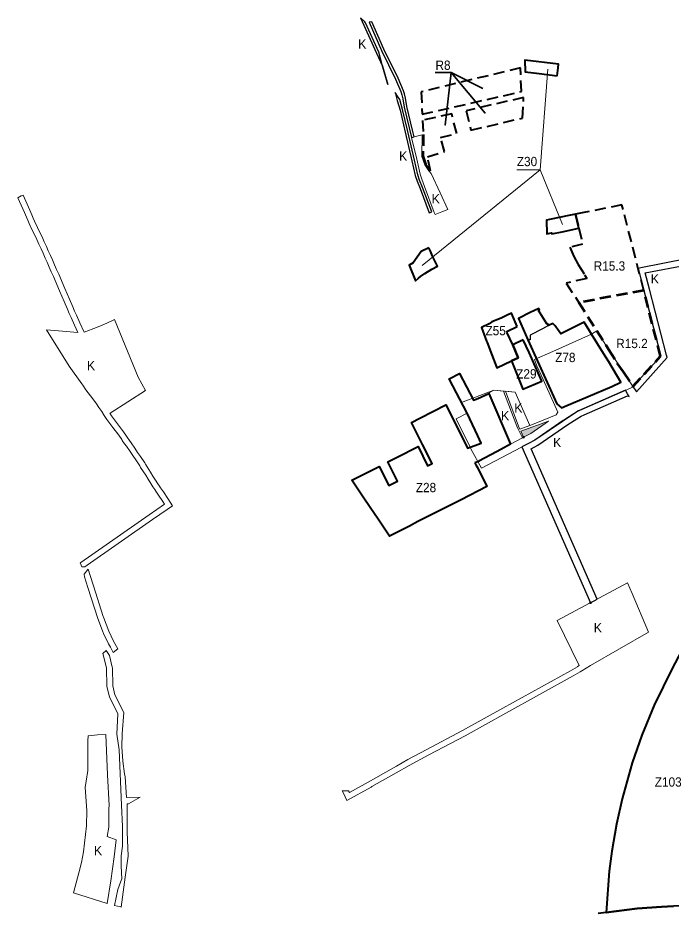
# Model space of a CAD drawing. Extents: x -650276 to -642489, y -1074311 to -1066658.
# Drawn here: x -649558 to -647871, y -1068970 to -1066658 of the extents above; entities that cross this region are included whole.
import ezdxf

# ---------------------------------------------------------------- set-up
doc = ezdxf.new("R2010")
doc.units = 0
doc.header["$LTSCALE"] = 9.6
doc.header["$PDMODE"] = 32
doc.header["$PDSIZE"] = 4.8
doc.linetypes.add('MEDIUM_DASHED', pattern=[4.5, 3, -1.5])
for name, color, linetype, lineweight in [('42', 7, 'Continuous', 25), ('44', 7, 'Continuous', 40), ('45', 7, 'Continuous', 40), ('46', 7, 'Continuous', 13), ('47', 7, 'Continuous', 13), ('48', 7, 'Continuous', 13), ('61', 7, 'MEDIUM_DASHED', 40), ('62', 7, 'Continuous', 35), ('63', 7, 'Continuous', 13)]:
    doc.layers.add(name, color=color, linetype=linetype, lineweight=lineweight)

msp = doc.modelspace()

# ---------------------------------------------------------------- hatches: boundary and pattern name
at = {"layer": '47'}
msp.add_hatch(color=256, dxfattribs=at).paths.add_polyline_path([(-648258.96, -1067725.37), (-648251.711, -1067741.124), (-648233.264, -1067731.288), (-648187.139, -1067699.179)])

# ---------------------------------------------------------------- linework, layer by layer
at = {"layer": '42'}
msp.add_lwpolyline([(-648153.98, -1067665.43), (-648149.933, -1067663.646), (-648146.21, -1067661.3), (-648023.96, -1067610.13), (-648000.63, -1067599.14), (-648031.77, -1067546.6), (-648045.04, -1067525.15), (-648076.32, -1067474.6), (-648081.31, -1067466.54), (-648095.28, -1067444.06), (-648133.56, -1067463.2), (-648150.46, -1067471.66), (-648155.85, -1067474.35), (-648164.24, -1067462.15), (-648166.97, -1067458.18), (-648170.38, -1067453.23), (-648175.94, -1067446.89), (-648187.44, -1067452.8), (-648203.39, -1067460.99), (-648234.68, -1067477.06), (-648234.87, -1067489.9), (-648240.51, -1067489.9), (-648166.173, -1067654.853)], close=True, dxfattribs=at)
at = {"layer": '44'}
for points in [[(-647801.168, -1068218.237), (-647843.6, -1068292.629), (-647868.214, -1068337.803), (-647914.339, -1068432.512), (-647946.187, -1068510.254), (-647971.074, -1068581.98), (-647997.27, -1068674.747), (-648011.775, -1068739.718), (-648023.914, -1068809.332), (-648030.73, -1068861.213), (-648038.596, -1068968.281), (-647958.168, -1068957.73)], [(-647749.978, -1068953.416), (-647850.043, -1068951.099), (-647864.531, -1068951.823), (-647895.901, -1068953.392), (-647958.168, -1068957.73), (-648038.596, -1068968.281), (-648038.596, -1068968.281), (-648038.746, -1068968.301), (-648058.764, -1068970.927)], [(-647958.168, -1068957.73), (-647895.901, -1068953.392), (-647864.531, -1068951.823)]]:
    msp.add_lwpolyline(points, dxfattribs=at)
at = {"layer": '45'}
for points in [[(-648165.33, -1066807.74), (-648162.8, -1066786.8), (-648161.58, -1066777.41), (-648248.77, -1066767.43), (-648247.78, -1066797.53), (-648211.58, -1066802.18)], [(-648165.33, -1066807.74), (-648162.8, -1066786.8), (-648161.58, -1066777.41), (-648248.77, -1066767.43), (-648247.78, -1066797.53), (-648211.58, -1066802.18)], [(-648185.185, -1067178.687), (-648193.02, -1067180.66), (-648191.44, -1067215.62), (-648179.42, -1067213.37), (-648179, -1067215.71), (-648152.5, -1067210.23), (-648109.1, -1067201.21), (-648117.51, -1067165.42), (-648131.01, -1067167.84)], [(-648185.185, -1067178.687), (-648193.02, -1067180.66), (-648191.44, -1067215.62), (-648179.42, -1067213.37), (-648179, -1067215.71), (-648152.5, -1067210.23), (-648109.1, -1067201.21), (-648117.51, -1067165.42), (-648131.01, -1067167.84)], [(-648496.55, -1067251.53), (-648516.47, -1067261.54), (-648536.84, -1067290.29), (-648547.17, -1067296.68), (-648531.51, -1067337.57), (-648523.55, -1067330.33), (-648518.55, -1067326.3), (-648507.25, -1067318.35), (-648488.66, -1067307.11), (-648474.69, -1067299.66), (-648486.79, -1067273.26), (-648492.62, -1067260.53)], [(-648496.55, -1067251.53), (-648516.47, -1067261.54), (-648536.84, -1067290.29), (-648547.17, -1067296.68), (-648531.51, -1067337.57), (-648523.55, -1067330.33), (-648518.55, -1067326.3), (-648507.25, -1067318.35), (-648488.66, -1067307.11), (-648474.69, -1067299.66), (-648486.79, -1067273.26), (-648492.62, -1067260.53)], [(-648153.98, -1067665.43), (-648149.933, -1067663.646), (-648146.21, -1067661.3), (-648023.96, -1067610.13), (-648000.63, -1067599.14), (-648031.77, -1067546.6), (-648045.04, -1067525.15), (-648076.32, -1067474.6), (-648081.31, -1067466.54), (-648095.28, -1067444.06), (-648133.56, -1067463.2), (-648150.46, -1067471.66), (-648155.85, -1067474.35), (-648164.24, -1067462.15), (-648166.97, -1067458.18), (-648170.38, -1067453.23), (-648175.94, -1067446.89), (-648187.44, -1067452.8), (-648190.23, -1067447.83), (-648191.46, -1067448.59), (-648213.34, -1067413.46), (-648210.48, -1067411.68), (-648212.32, -1067408.39), (-648234.808, -1067419.29), (-648265.197, -1067434.03), (-648240.51, -1067489.9), (-648166.173, -1067654.853)], [(-648153.98, -1067665.43), (-648149.933, -1067663.646), (-648146.21, -1067661.3), (-648023.96, -1067610.13), (-648000.63, -1067599.14), (-648031.77, -1067546.6), (-648045.04, -1067525.15), (-648076.32, -1067474.6), (-648081.31, -1067466.54), (-648095.28, -1067444.06), (-648133.56, -1067463.2), (-648150.46, -1067471.66), (-648155.85, -1067474.35), (-648164.24, -1067462.15), (-648166.97, -1067458.18), (-648170.38, -1067453.23), (-648175.94, -1067446.89), (-648187.44, -1067452.8), (-648190.23, -1067447.83), (-648191.46, -1067448.59), (-648213.34, -1067413.46), (-648210.48, -1067411.68), (-648212.32, -1067408.39), (-648234.808, -1067419.29), (-648265.197, -1067434.03), (-648240.51, -1067489.9), (-648166.173, -1067654.853)], [(-648253.1, -1067489.23), (-648279.86, -1067502.11), (-648265.757, -1067535.555), (-648282.863, -1067543.596), (-648254.04, -1067616.96), (-648204.88, -1067596.54), (-648237.81, -1067522.42)]]:
    msp.add_lwpolyline(points, close=True, dxfattribs=at)
for points in [[(-648268.67, -1067455.43), (-648283.21, -1067420.88), (-648295.66, -1067426.76), (-648309.57, -1067433.34), (-648333.48, -1067443.28), (-648341.15, -1067448.14)], [(-648341.15, -1067448.14), (-648361, -1067457.36), (-648347.51, -1067492.87)], [(-648279.86, -1067502.11), (-648294.04, -1067471.35), (-648295.409, -1067468.129), (-648268.67, -1067455.43)], [(-648347.51, -1067492.87), (-648346.27, -1067496.14), (-648334.09, -1067528.2), (-648321.36, -1067561.69), (-648282.863, -1067543.596)], [(-648282.863, -1067543.596), (-648265.757, -1067535.555), (-648279.86, -1067502.11)], [(-648433.183, -1067696.369), (-648396.605, -1067769.277), (-648387.04, -1067765.67), (-648361.08, -1067755.88), (-648369.832, -1067737.624), (-648397.98, -1067678.79), (-648443.83, -1067589.92), (-648417.12, -1067576.17), (-648381.535, -1067645.274), (-648369.949, -1067640.851), (-648342.023, -1067628.096), (-648285.254, -1067759.008), (-648310.511, -1067772.476), (-648321.623, -1067778.399), (-648367.811, -1067802.994), (-648370.113, -1067804.22), (-648377.422, -1067807.337)], [(-648377.422, -1067807.337), (-648374.84, -1067812.43), (-648371.27, -1067819.47), (-648346.57, -1067868.56), (-648413.41, -1067902.53), (-648524.72, -1067958.93), (-648546.76, -1067970.44), (-648597.93, -1067996.72), (-648629.22, -1067950.214), (-648635.249, -1067941.252), (-648664.41, -1067897.91), (-648695.27, -1067852.04), (-648668.085, -1067838.186), (-648624.76, -1067816.11), (-648600.14, -1067865.29), (-648577.78, -1067854.07), (-648602.3, -1067804.83), (-648580.14, -1067793.61), (-648524.44, -1067765.11), (-648499.7, -1067814.37), (-648488.49, -1067808.76), (-648513.23, -1067759.38), (-648516.73, -1067752.57), (-648541.86, -1067702.86), (-648519.63, -1067691.58), (-648452.72, -1067657.62), (-648433.183, -1067696.369)]]:
    msp.add_lwpolyline(points, dxfattribs=at)
at = {"layer": '46'}
msp.add_lwpolyline([(-648269.459, -1067050.713), (-648208.812, -1067050.713), (-648188.893, -1066790.602), (-648208.812, -1067050.713), (-648151.62, -1067191.569), (-648208.812, -1067050.713), (-648513.485, -1067297.251)], dxfattribs=at)
msp.add_lwpolyline([(-648269.459, -1067050.713), (-648208.812, -1067050.713), (-648188.893, -1066790.602), (-648208.812, -1067050.713), (-648151.62, -1067191.569), (-648208.812, -1067050.713), (-648513.485, -1067297.251)], dxfattribs=at)
at = {"layer": '47'}
msp.add_line((-648108.158, -1068330.583), (-648112.198, -1068333.037), dxfattribs=at)
at = {"layer": '47', "lineweight": 25}
for points in [[(-648602.97, -1066830.11), (-648616.86, -1066779.79), (-648625.44, -1066746.45), (-648659.95, -1066670.89), (-648662.46, -1066668.53), (-648673.407, -1066658.275), (-648631.791, -1066749.394)], [(-648534.701, -1066965.077), (-648538.812, -1066947.891), (-648553.323, -1066887.238), (-648556.637, -1066865.397), (-648559.94, -1066854.66), (-648562.542, -1066846.219), (-648576.145, -1066813.802), (-648612.763, -1066739.165), (-648643.925, -1066668.483), (-648651.042, -1066669.551), (-648651.1, -1066669.56)], [(-648651.1, -1066669.56), (-648619.11, -1066742.12), (-648582.52, -1066816.7)], [(-648631.791, -1066749.394), (-648616.104, -1066782.727), (-648602.97, -1066830.11)], [(-648582.52, -1066816.7), (-648569.13, -1066848.61), (-648566.63, -1066856.72), (-648563.48, -1066866.96), (-648560.2, -1066888.58), (-648541.521, -1066966.657), (-648534.701, -1066965.077)], [(-648571.96, -1066869.37), (-648577.99, -1066860.17), (-648583.94, -1066851.11)], [(-648583.94, -1066851.11), (-648578.702, -1066871.259), (-648571.167, -1066896.326), (-648557.816, -1066953.444)], [(-648489.1, -1067158.84), (-648512.95, -1067095.97), (-648520.4, -1067077.42), (-648524.93, -1067063.35), (-648533.66, -1067026), (-648551, -1066951.85), (-648564.4, -1066894.52), (-648571.96, -1066869.37)], [(-648557.816, -1066953.444), (-648540.476, -1067027.594), (-648531.681, -1067065.222)], [(-648531.681, -1067065.222), (-648526.988, -1067079.8), (-648519.471, -1067098.516), (-648495.644, -1067161.326), (-648489.1, -1067158.84)], [(-647882.66, -1067529.231), (-647926.759, -1067358.379), (-647937.355, -1067316.774), (-647828.376, -1067295.406), (-647828.104, -1067295.352), (-647831.28, -1067280.69), (-647948.488, -1067303.671)], [(-647948.488, -1067303.671), (-647955.805, -1067305.106), (-647941.289, -1067362.104)], [(-647941.289, -1067362.104), (-647897.637, -1067531.223), (-647969.29, -1067609.79), (-647959.832, -1067623.65)], [(-647959.832, -1067623.65), (-647881.085, -1067535.333), (-647882.66, -1067529.231)], [(-647978.705, -1067635.817), (-647982.95, -1067628.73), (-647988.334, -1067619.747), (-648046.773, -1067645.314)], [(-648046.773, -1067645.314), (-648110.36, -1067673.133), (-648146.127, -1067695.8), (-648146.146, -1067695.813), (-648149.529, -1067698.132), (-648222.53, -1067748.178)], [(-648095.475, -1067682.994), (-647983.06, -1067633.813), (-647978.705, -1067635.817)], [(-648232.676, -1067770.513), (-648215.115, -1067761.28), (-648137.869, -1067708.325), (-648114.323, -1067693.403), (-648103.298, -1067686.416), (-648095.475, -1067682.994)], [(-648238.748, -1067756.759), (-648256.499, -1067766.091), (-648079.002, -1068168.139)], [(-648222.53, -1067748.178), (-648222.872, -1067748.412), (-648238.748, -1067756.759)], [(-648079.002, -1068168.139), (-648061.329, -1068158.649), (-648232.676, -1067770.513)]]:
    msp.add_lwpolyline(points, dxfattribs=at)
at = {"layer": '47'}
for points in [[(-648490.23, -1067060.06), (-648496.87, -1067053.5), (-648506.78, -1067037.81), (-648514.38, -1067016.2), (-648513.842, -1066960.243), (-648541.52, -1066966.657), (-648528.01, -1067023.13)], [(-648528.01, -1067023.13), (-648518.72, -1067061.99), (-648514.86, -1067074.83), (-648507.88, -1067093.9), (-648483.31, -1067160.63), (-648480.57, -1067166.13)], [(-648480.57, -1067166.13), (-648462.97, -1067159.24), (-648447.66, -1067153.25), (-648467.56, -1067110.02), (-648490.23, -1067060.06)], [(-649545.203, -1067115.647), (-649549.7, -1067118.05), (-649558.469, -1067122.73), (-649541.537, -1067160.722), (-649536.075, -1067172.622), (-649532.831, -1067180.855), (-649529.013, -1067189.389), (-649521.663, -1067206.124), (-649514.869, -1067218.957), (-649509.44, -1067230.141), (-649504.224, -1067242.225), (-649498.572, -1067254.427), (-649493.526, -1067265.611), (-649487.812, -1067278.312), (-649482.963, -1067288.934), (-649477.677, -1067301.655), (-649472.327, -1067313.644), (-649466.703, -1067326.24), (-649451.059, -1067363.074), (-649439.265, -1067390.397), (-649430.531, -1067410.689), (-649425.804, -1067421.21), (-649421.071, -1067431.944), (-649411.913, -1067451.746), (-649403.34, -1067470.579)], [(-649387.17, -1067469.894), (-649398.28, -1067445.49), (-649407.4, -1067425.77), (-649412.1, -1067415.11), (-649416.8, -1067404.65), (-649425.49, -1067384.46), (-649437.27, -1067357.17), (-649452.95, -1067320.25), (-649458.63, -1067307.53), (-649463.9, -1067295.72), (-649469.21, -1067282.94), (-649474.15, -1067272.12), (-649479.85, -1067259.45), (-649484.93, -1067248.19), (-649490.53, -1067236.1), (-649495.8, -1067223.89), (-649501.49, -1067212.17), (-649508.15, -1067199.59), (-649515.3, -1067183.31), (-649519, -1067175.04), (-649522.27, -1067166.74), (-649527.87, -1067154.54), (-649545.203, -1067115.647)], [(-649321.3, -1067679), (-649320.47, -1067678.44), (-649228.52, -1067620.294), (-649247.518, -1067586.255), (-649308.75, -1067437.11), (-649329.068, -1067446.175), (-649355.44, -1067457.94), (-649387.17, -1067469.894)], [(-649403.34, -1067470.579), (-649453.39, -1067466.13), (-649484.28, -1067463.88), (-649425.69, -1067557.7), (-649393.23, -1067603.28), (-649391.04, -1067606.27), (-649382.53, -1067618.33), (-649364.69, -1067641.98), (-649355.46, -1067654.85), (-649349.12, -1067663.84), (-649341.81, -1067674.33), (-649335.26, -1067685.21), (-649333.74, -1067687.4)], [(-649333.74, -1067687.4), (-649328.34, -1067694.79), (-649317.99, -1067708.85), (-649312.91, -1067715.45), (-649298.02, -1067735.58), (-649290.15, -1067746.92), (-649288.63, -1067748.97), (-649282.85, -1067757.79), (-649278.14, -1067764.31), (-649268.46, -1067777.97), (-649261.48, -1067788.47), (-649253.98, -1067799.2), (-649243.37, -1067815.17), (-649241.28, -1067818.7), (-649228.27, -1067839.26), (-649222.11, -1067849.12), (-649215.32, -1067859.99), (-649209.39, -1067869.34), (-649204.87, -1067875.85), (-649202.02, -1067880.07), (-649194.77, -1067890.67), (-649184, -1067906.88), (-649179.96, -1067913.35), (-649219.088, -1067940.964), (-649395.729, -1068064.23), (-649397.466, -1068065.442), (-649394.83, -1068071.05), (-649392.88, -1068075.9), (-649385.41, -1068075.32), (-649379.295, -1068071.053), (-649210.54, -1067953.29), (-649172.99, -1067927.41), (-649159.179, -1067918.309), (-649171.389, -1067898.756), (-649182.332, -1067882.285), (-649189.614, -1067871.638), (-649192.493, -1067867.375), (-649196.89, -1067861.042), (-649202.625, -1067852), (-649209.388, -1067841.173), (-649215.571, -1067831.276), (-649228.486, -1067810.867), (-649230.661, -1067807.193), (-649241.584, -1067790.752), (-649249.085, -1067780.02), (-649256.092, -1067769.48), (-649265.941, -1067755.582), (-649270.491, -1067749.283), (-649276.322, -1067740.385), (-649277.961, -1067738.175), (-649285.826, -1067726.842), (-649300.936, -1067706.414), (-649306.005, -1067699.828), (-649316.244, -1067685.919), (-649321.3, -1067679)], [(-649376.467, -1068081.552), (-649377.77, -1068082.44), (-649387.46, -1068094.51), (-649386.74, -1068101.31), (-649377.81, -1068129), (-649352.11, -1068208.65)], [(-649352.11, -1068208.65), (-649339.94, -1068241.13), (-649337.52, -1068247.59), (-649324.66, -1068274.3), (-649319.551, -1068283.382), (-649312.087, -1068296.653), (-649300.305, -1068287.002), (-649311.352, -1068267.362), (-649323.711, -1068241.693), (-649337.178, -1068205.751), (-649337.942, -1068203.713), (-649363.534, -1068124.395), (-649371.987, -1068098.185), (-649376.467, -1068081.552)], [(-648101.42, -1068344.28), (-648079.33, -1068330.03), (-647929.45, -1068244.16), (-647971.35, -1068144.48), (-647982.969, -1068116.575), (-648165.28, -1068214.465), (-648108.158, -1068330.583)], [(-649330.038, -1068291.976), (-649339.046, -1068299.359), (-649329.644, -1068336.779), (-649328.386, -1068384.468), (-649321.727, -1068411.472), (-649299.894, -1068454.728), (-649302.681, -1068507.363)], [(-649289.24, -1068506.8), (-649284.59, -1068451.76), (-649307.57, -1068406.23), (-649313.42, -1068382.51), (-649314.27, -1068336.41), (-649314.693, -1068334.727), (-649322.18, -1068304.93), (-649330.038, -1068291.976)], [(-648112.198, -1068333.037), (-648112.92, -1068333.424), (-648131.034, -1068344.388), (-648305.242, -1068440.3), (-648410.111, -1068498.408), (-648503.768, -1068547.914), (-648551.041, -1068573.16)], [(-648547.25, -1068588.14), (-648496.73, -1068561.16), (-648402.97, -1068511.6), (-648297.99, -1068453.43), (-648123.53, -1068357.38), (-648105.49, -1068346.46), (-648101.42, -1068344.28)], [(-649327.679, -1068945.222), (-649318.13, -1068886.42), (-649314.07, -1068855.33), (-649310.01, -1068824.2), (-649304.66, -1068780.33), (-649327.8, -1068771.82), (-649323.68, -1068748.06), (-649323.1, -1068699.28), (-649323.02, -1068692.1), (-649326.53, -1068612.89), (-649331.151, -1068508.557), (-649353.17, -1068509.48), (-649376.77, -1068511.96), (-649377.52, -1068525.1), (-649377.56, -1068564.89), (-649378.08, -1068601.24), (-649382.46, -1068629.34), (-649384.31, -1068644.92), (-649379.97, -1068704.98), (-649381.06, -1068744.69), (-649383.78, -1068766.6)], [(-649302.681, -1068507.363), (-649296.55, -1068548.09), (-649290.93, -1068690.93), (-649287.98, -1068745.74), (-649288.19, -1068786.39), (-649288.24, -1068796.6), (-649291.64, -1068821.88), (-649291.87, -1068848.02), (-649290.28, -1068880.82), (-649293.33, -1068889.65), (-649299.91, -1068908.66), (-649308.65, -1068950), (-649293.04, -1068953.81), (-649291.32, -1068954.23), (-649281.01, -1068876.69), (-649273.66, -1068822.58), (-649275.96, -1068759.73), (-649276.43, -1068688.29), (-649276.474, -1068687.673), (-649272.755, -1068687.618)], [(-649277.655, -1068670.983), (-649281.4, -1068618.05), (-649282.97, -1068610.04), (-649287.71, -1068577.14), (-649289.74, -1068540.2), (-649289.24, -1068506.8)], [(-648551.041, -1068573.16), (-648580.062, -1068590.087), (-648588.022, -1068594.571), (-648653.034, -1068631.191), (-648701.568, -1068658.36), (-648703.816, -1068653.711), (-648720.238, -1068654.205)], [(-648720.238, -1068654.205), (-648717.32, -1068660.24), (-648708.14, -1068679.23), (-648645.69, -1068644.27), (-648643.654, -1068643.123), (-648580.66, -1068607.64), (-648547.25, -1068588.14)], [(-649272.755, -1068687.618), (-649272.69, -1068687.58), (-649242.507, -1068669.925), (-649277.655, -1068670.983)], [(-649383.78, -1068766.6), (-649389.34, -1068811.43), (-649394.48, -1068838.89), (-649401.31, -1068865.78), (-649415.09, -1068917.1), (-649327.679, -1068945.222)]]:
    msp.add_lwpolyline(points, dxfattribs=at)
for points in [[(-648303.68, -1067621.697), (-648328.54, -1067619.51), (-648342.697, -1067626.806), (-648296.891, -1067732.172), (-648285.254, -1067759.008), (-648255.016, -1067742.886), (-648265.614, -1067720.378), (-648269.27, -1067712.6)], [(-648298.632, -1067622.141), (-648273.229, -1067624.376), (-648235.78, -1067710.79), (-648261.25, -1067720.39), (-648265.08, -1067712.06)], [(-648258.96, -1067725.37), (-648251.711, -1067741.124), (-648233.264, -1067731.288), (-648187.139, -1067699.179)]]:
    msp.add_lwpolyline(points, close=True, dxfattribs=at)
for p in [(-648251.711, -1067741.124), (-648079.002, -1068168.139)]:
    msp.add_point(p, dxfattribs=at)
at = {"layer": '61'}
for points in [[(-648259.725, -1066787.254), (-648516.098, -1066849.061), (-648514.246, -1066907.231), (-648257.498, -1066848.545)], [(-648251.815, -1066863.877), (-648400.574, -1066897.877), (-648387.967, -1066948.136), (-648254.98, -1066916.96)], [(-648437.487, -1066905.774), (-648513.271, -1066923.097), (-648510.55, -1066959.48), (-648511.02, -1067015.58), (-648504.44, -1067035.85), (-648492.67, -1067053.5), (-648500.15, -1067017.22), (-648456.62, -1067003.59), (-648466.26, -1066967), (-648424.66, -1066956.87)]]:
    msp.add_lwpolyline(points, close=True, dxfattribs=at)
for points in [[(-647941.289, -1067362.104), (-647997.58, -1067141.08), (-648095.81, -1067160.82), (-648117.51, -1067165.42), (-648109.1, -1067201.21), (-648099.39, -1067242.54)], [(-648099.39, -1067242.54), (-648132.22, -1067250.27), (-648121.94, -1067274.29), (-648110.97, -1067294.96), (-648094.1, -1067322.05), (-648088.84, -1067331.19), (-648141.82, -1067342.88), (-648108.77, -1067393.23)]]:
    msp.add_lwpolyline(points, dxfattribs=at)
at = {"layer": '61', "lineweight": 53}
for points in [[(-647941.289, -1067362.104), (-648108.77, -1067393.23), (-648031.228, -1067515.162), (-648010.57, -1067549.31)], [(-648010.57, -1067549.31), (-647994.8, -1067572.37), (-647969.29, -1067609.79), (-647898.091, -1067531.72), (-647941.289, -1067362.104)]]:
    msp.add_lwpolyline(points, dxfattribs=at)
at = {"layer": '62'}
msp.add_lwpolyline([(-648480.094, -1066799.151), (-648438.938, -1066799.151), (-648454.468, -1066935.138), (-648438.938, -1066799.151), (-648351.131, -1066904.144), (-648438.938, -1066799.151), (-648357.401, -1066840.335)], dxfattribs=at)
at = {"layer": '62', "lineweight": 13}
msp.add_lwpolyline([(-648480.094, -1066799.151), (-648438.938, -1066799.151), (-648454.468, -1066935.138), (-648438.938, -1066799.151), (-648351.131, -1066904.144), (-648438.938, -1066799.151), (-648357.401, -1066840.335)], dxfattribs=at)
at = {"layer": '63'}
for points in [[(-648062.609, -1067466.599), (-648076.32, -1067474.6), (-648176.4, -1067519.99), (-648224, -1067540.44), (-648217.85, -1067556.39), (-648201.42, -1067592.09), (-648163.11, -1067676.17), (-648167.48, -1067683.45), (-648219.86, -1067704.42), (-648235.78, -1067710.79), (-648273.229, -1067624.376), (-648328.54, -1067619.51), (-648412.003, -1067651.62), (-648397.98, -1067678.79), (-648424.69, -1067692.54), (-648426.366, -1067693.402), (-648389.29, -1067768.64)], [(-648360.993, -1067821.027), (-648222.872, -1067748.412), (-648114.145, -1067675.531), (-647988.235, -1067619.912), (-647968.536, -1067610.864), (-648035.38, -1067509.89), (-648062.609, -1067466.599)], [(-648389.29, -1067768.64), (-648387.46, -1067772.25), (-648360.993, -1067821.027)]]:
    msp.add_lwpolyline(points, dxfattribs=at)

# ---------------------------------------------------------------- texts
at = {"layer": '44', "width": 0.95}
msp.add_text('Z103', height=24, dxfattribs=at).set_placement((-647912.849, -1068643.055))
at = {"layer": '46', "width": 0.95}
for s, p in [('Z30', (-648269.261, -1067041.062)), ('Z30', (-648269.261, -1067041.062)), ('Z55', (-648350.312, -1067477.755)), ('Z78', (-648170.304, -1067546.968)), ('Z29', (-648270.915, -1067589.341)), ('Z28', (-648530.318, -1067882.806))]:
    msp.add_text(s, height=24, dxfattribs=at).set_placement(p)
at = {"layer": '48'}
for p in [(-648679.318, -1066737.684), (-648573.703, -1067027.067), (-648489.516, -1067137.308), (-648489.516, -1067137.308), (-647923.173, -1067344.01), (-649380.314, -1067568.167), (-649380.314, -1067568.167), (-648276.169, -1067677.278), (-648310.251, -1067697.408), (-648175.732, -1067766.601), (-648070.59, -1068244.82), (-648070.59, -1068244.82), (-649362.16, -1068820.233), (-649362.16, -1068820.233)]:
    msp.add_text('K', height=24, dxfattribs=at).set_placement(p)
at = {"layer": '62', "width": 0.95}
for s, p in [('R8', (-648479.548, -1066792.4)), ('R8', (-648479.548, -1066792.4)), ('R15.3', (-648070.747, -1067310.744)), ('R15.2', (-648012.511, -1067510.868))]:
    msp.add_text(s, height=24, dxfattribs=at).set_placement(p)

doc.saveas('drawing.dxf')
